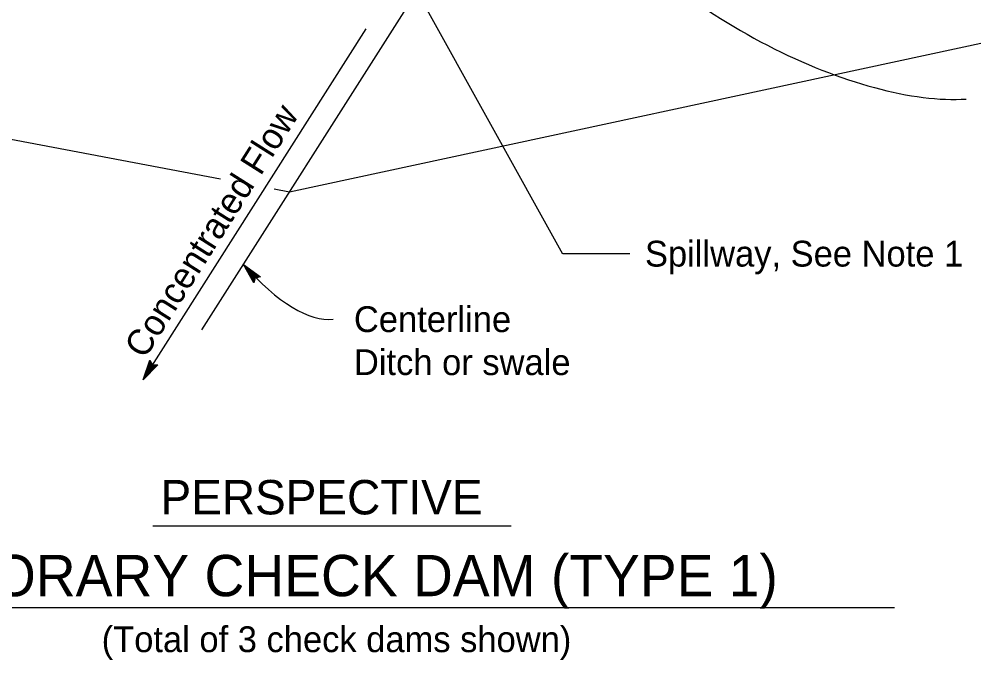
# Model space of a CAD drawing. Extents: x 6707406 to 6714471, y 1868570 to 1872341.
# Drawn here: x 6707639.7 to 6707906.2, y 1870014 to 1870192.8 of the extents above; entities that cross this region are included whole.
import ezdxf

# ---------------------------------------------------------------- set-up
doc = ezdxf.new("R2010")
doc.units = 0
for name, color, linetype in [('56 Stg 3 Anno', 7, 'Continuous'), ('57 Undefined', 7, 'Continuous'), ('60 Nongeo Data', 7, 'Continuous')]:
    doc.layers.add(name, color=color, linetype=linetype)

msp = doc.modelspace()

# ---------------------------------------------------------------- linework, layer by layer
at = {"layer": '56 Stg 3 Anno'}
for p, q in [((6707737.98, 1870223.41), (6707791.39, 1870127.24)), ((6707674.27, 1870092.09), (6707736.61, 1870190.07)), ((6707810.13, 1870127.33), (6707791.57, 1870127.33)), ((6707705.17, 1870119.15), (6707702.29, 1870124.3)), ((6707702.29, 1870124.3), (6707702.29, 1870124.3)), ((6707702.29, 1870124.3), (6707707.08, 1870120.86)), ((6707705.28, 1870119.53), (6707703.17, 1870123.31)), ((6707703.18, 1870123.31), (6707706.67, 1870120.8)), ((6707705.39, 1870119.93), (6707704.05, 1870122.32)), ((6707704.05, 1870122.32), (6707706.31, 1870120.7)), ((6707705.53, 1870120.28), (6707704.94, 1870121.33)), ((6707704.94, 1870121.33), (6707705.9, 1870120.64)), ((6707705.61, 1870120.58), (6707705.17, 1870119.15)), ((6707707.08, 1870120.86), (6707705.61, 1870120.58)), ((6707707.08, 1870120.86), (6707707.08, 1870120.86)), ((6707705.17, 1870119.15), (6707705.17, 1870119.15)), ((6707674.27, 1870092.09), (6707676.2, 1870097.66)), ((6707678.38, 1870096.31), (6707674.27, 1870092.09)), ((6707674.96, 1870093.22), (6707676.38, 1870097.29)), ((6707677.98, 1870096.32), (6707674.96, 1870093.21)), ((6707675.66, 1870094.34), (6707676.57, 1870096.97)), ((6707677.57, 1870096.31), (6707675.66, 1870094.34)), ((6707676.2, 1870097.66), (6707676.2, 1870097.66)), ((6707676.2, 1870097.66), (6707676.89, 1870096.33)), ((6707676.36, 1870095.47), (6707676.75, 1870096.59)), ((6707677.2, 1870096.34), (6707676.36, 1870095.47)), ((6707676.89, 1870096.33), (6707678.38, 1870096.31)), ((6707678.38, 1870096.31), (6707678.38, 1870096.31)), ((6707674.27, 1870092.09), (6707674.27, 1870092.09))]:
    msp.add_line(p, q, dxfattribs=at)
for centre, major_axis, ratio, start_param, end_param in [((6707855.02, 1870222.1), (68.84, -42.22), 0.434429, 4.031868, 5.732815), ((6707701.11, 1870170.81), (-29.01, 60.95), 0.360833, 2.25187, 3.024453)]:
    msp.add_ellipse(centre, major_axis=major_axis, ratio=ratio, start_param=start_param, end_param=end_param, dxfattribs=at)
at = {"layer": '57 Undefined'}
for p, q in [((6707677.02, 1870051.42), (6707777.06, 1870051.42)), ((6707571.95, 1870028.6), (6707884.02, 1870028.6))]:
    msp.add_line(p, q, dxfattribs=at)
at = {"layer": '60 Nongeo Data'}
msp.add_line((6707690.72, 1870106.12), (6707748.46, 1870196.87), dxfattribs=at)
for points in [[(6707486.86, 1870187.72), (6707695.92, 1870148.21)], [(6707715.19, 1870144.57), (6707919.37, 1870188.45)], [(6707710.87, 1870145.39), (6707715.18, 1870144.57)]]:
    msp.add_lwpolyline(points, dxfattribs=at)

# ---------------------------------------------------------------- texts
at = {"layer": '57 Undefined'}
msp.add_text('Concentrated Flow', height=7.2002, rotation=57.6809, dxfattribs=at).set_placement((6707674.76, 1870097.7))
for s, height, p in [('Spillway, See Note 1', 7.2002, (6707814.39, 1870123.73)), ('Centerline', 7.2, (6707733.15, 1870105.46)), ('Ditch or swale', 7.2002, (6707733.15, 1870093.46)), ('PERSPECTIVE', 9.6002, (6707679.15, 1870054.58)), ('TEMPORARY CHECK DAM (TYPE 1)', 11.5203, (6707589.57, 1870031.75)), ('(Total of 3 check dams shown)', 7.2002, (6707662.73, 1870016.15))]:
    msp.add_text(s, height=height, dxfattribs=at).set_placement(p)

doc.saveas('drawing.dxf')
